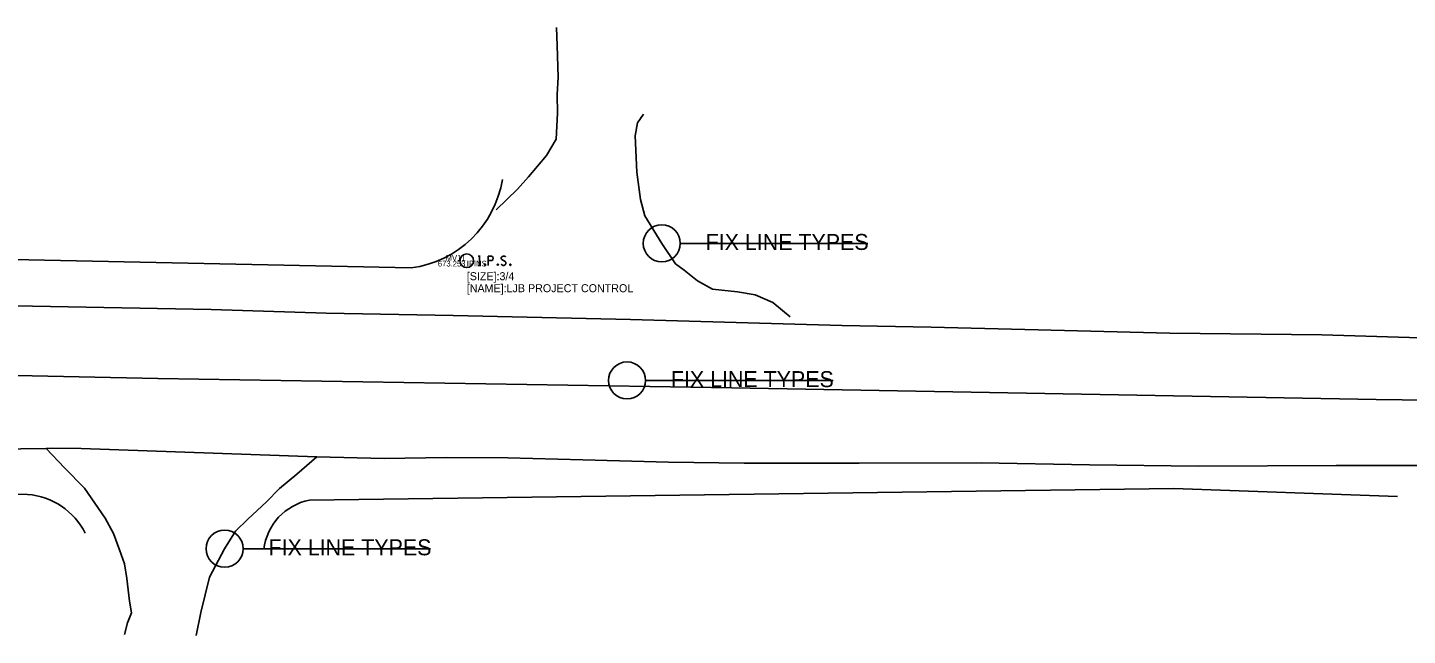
# Model space of a CAD drawing. Extents: x 1659932 to 1663108, y 619867 to 620611.
# Drawn here: x 1662378.6 to 1662620, y 620165.8 to 620272.2 of the extents above; entities that cross this region are included whole.
import ezdxf

# ---------------------------------------------------------------- set-up
doc = ezdxf.new("R2010")
doc.units = 0
for name, color, linetype in [('PM_X_CL_Dashed', 7, 'Continuous'), ('PV_X_Driveway', 7, 'Continuous'), ('PV_X_EOP', 7, 'Continuous'), ('RD_X_GR_Lt', 7, 'Continuous'), ('RD_X_GR_Rt', 7, 'Continuous'), ('RS_Raster1', 7, 'Continuous'), ('SC_Scratch6', 7, 'Continuous'), ('SV_P_Mon_Cells_Set_Text', 7, 'Continuous'), ('SV_X_Text_Comment', 7, 'Continuous'), ('SV_X_Text_Elevation', 7, 'Continuous'), ('SV_X_Text_Name', 7, 'Continuous')]:
    doc.layers.add(name, color=color, linetype=linetype)

msp = doc.modelspace()

# ---------------------------------------------------------------- linework, layer by layer
at = {"layer": 'PM_X_CL_Dashed'}
msp.add_lwpolyline([(1661548.68, 620227.77), (1661669.96, 620225.42), (1661783.14, 620222.83), (1661893.22, 620220.99), (1661995.64, 620218.69), (1662098.65, 620216.83), (1662208.49, 620214.49), (1662310.47, 620212.73), (1662401.36, 620210.77), (1662501.77, 620209.17), (1662614.52, 620207.13), (1662727.83, 620205.67), (1662841.02, 620204.32), (1662955.43, 620202.56), (1663049.21, 620201.36)], dxfattribs=at)
at = {"layer": 'PV_X_Driveway'}
for points in [[(1662460.54, 620240.32), (1662464.25, 620243.92), (1662466.2, 620246.07), (1662469.37, 620249.77), (1662471.06, 620252.67), (1662471.28, 620257.18), (1662471.19, 620260.47), (1662471.38, 620263.53), (1662471.2, 620269.05), (1662471.11, 620272.17)], [(1662511.97, 620221.55), (1662508.94, 620224.1), (1662505.83, 620225.43), (1662502.79, 620225.92), (1662498.37, 620226.39), (1662495.76, 620227.86), (1662493.42, 620229.75), (1662491.9, 620230.87), (1662489.52, 620234.43), (1662486.58, 620239.22), (1662485.8, 620242.11), (1662485.16, 620246.91), (1662484.89, 620253.23), (1662485.25, 620255.52), (1662486.3, 620257.05)], [(1662381.78, 620198.56), (1662385.01, 620195.16), (1662388.52, 620191.58), (1662392.1, 620186.32), (1662393.58, 620183.64), (1662394.66, 620180.8), (1662395.49, 620178.34), (1662395.91, 620175.79), (1662396.39, 620171.8), (1662396.76, 620169.81), (1662396.05, 620168.02), (1662395.49, 620166)], [(1662429.15, 620197.06), (1662425.64, 620194.03), (1662422.64, 620191.53), (1662420.35, 620189.19), (1662417.11, 620186.15), (1662414.93, 620184.09), (1662413.03, 620181.01), (1662411.42, 620178.02), (1662410.38, 620176.03), (1662408.87, 620169.82), (1662408.07, 620165.84)]]:
    msp.add_lwpolyline(points, dxfattribs=at)
at = {"layer": 'PV_X_EOP'}
for points in [[(1662356.1, 620223.94), (1662379.4, 620223.45), (1662410.67, 620222.83), (1662430.81, 620222.24), (1662453.03, 620221.83), (1662484.05, 620221.11), (1662521.05, 620220.08), (1662536.67, 620219.77), (1662553.06, 620219.35), (1662578.43, 620218.71), (1662605, 620218.4), (1662626.13, 620217.78), (1662672.55, 620217.65), (1662695.2, 620217.2), (1662709.6, 620217.07), (1662729.62, 620215.99), (1662750.02, 620215.7)], [(1662368.44, 620198.38), (1662381.78, 620198.56), (1662382.87, 620198.57), (1662387.9, 620198.53), (1662429.15, 620197.06), (1662440.92, 620196.76), (1662451.85, 620196.96), (1662462.59, 620196.88), (1662475.72, 620196.55), (1662490.67, 620196.16), (1662503.91, 620195.98), (1662524.07, 620195.98), (1662545.42, 620196), (1662564.38, 620195.66), (1662583.42, 620195.47), (1662607.51, 620195.55), (1662625.5, 620195.59), (1662642.9, 620195.66), (1662666.6, 620195.5), (1662681.6, 620195.32), (1662697.07, 620195.69), (1662737.7, 620195.47), (1662777.34, 620194.96)]]:
    msp.add_lwpolyline(points, dxfattribs=at)
at = {"layer": 'RD_X_GR_Lt'}
msp.add_line((1662112.15, 620237.06), (1662445.65, 620230.14), dxfattribs=at)
msp.add_arc((1662443.24, 620248.64), 18.66, 277.4288, 350.6729, dxfattribs=at)
at = {"layer": 'RD_X_GR_Rt'}
for p, q in [((1662114.92, 620196.42), (1662378.55, 620190.5)), ((1662427.87, 620189.49), (1662579.1, 620191.55)), ((1662579.1, 620191.55), (1662618.25, 620190.16))]:
    msp.add_line(p, q, dxfattribs=at)
for centre, radius, start, end in [((1662377.61, 620178.2), 12.33, 26.5223, 85.6298), ((1662429.75, 620179.74), 9.93, 100.9088, 173.3472)]:
    msp.add_arc(centre, radius, start, end, dxfattribs=at)
at = {"layer": 'RS_Raster1'}
for points in [[(1662457.42, 620232.18), (1662457.77, 620232.18)], [(1662457.6, 620230.58), (1662457.6, 620232.18)], [(1662459.16, 620230.58), (1662459.16, 620232.18), (1662459.69, 620232.18), (1662459.75, 620232.17), (1662459.82, 620232.15), (1662459.86, 620232.12), (1662459.89, 620232.1), (1662459.94, 620232.03), (1662459.97, 620231.97), (1662459.99, 620231.87), (1662459.99, 620231.72), (1662459.98, 620231.67), (1662459.96, 620231.59), (1662459.91, 620231.5), (1662459.87, 620231.47), (1662459.84, 620231.44), (1662459.78, 620231.42), (1662459.69, 620231.4), (1662459.16, 620231.4)], [(1662462.17, 620232.07), (1662462.15, 620232.1), (1662462.12, 620232.12), (1662462.02, 620232.16), (1662461.9, 620232.18), (1662461.81, 620232.18), (1662461.78, 620232.18), (1662461.63, 620232.15), (1662461.51, 620232.07), (1662461.43, 620231.97), (1662461.41, 620231.87), (1662461.41, 620231.79), (1662461.43, 620231.69), (1662461.52, 620231.61), (1662462.13, 620231.23), (1662462.18, 620231.18), (1662462.21, 620231.13), (1662462.23, 620231.05), (1662462.23, 620230.98), (1662462.22, 620230.9), (1662462.21, 620230.85), (1662462.18, 620230.79), (1662462.16, 620230.74), (1662462.14, 620230.7), (1662462.11, 620230.66), (1662462.07, 620230.64), (1662462.03, 620230.61), (1662462, 620230.6), (1662461.9, 620230.58), (1662461.74, 620230.58), (1662461.64, 620230.61), (1662461.5, 620230.7), (1662461.41, 620230.77)], [(1662457.42, 620230.58), (1662457.77, 620230.58)], [(1662458.56, 620230.8), (1662458.61, 620230.8), (1662458.65, 620230.77), (1662458.68, 620230.72), (1662458.68, 620230.66), (1662458.65, 620230.61), (1662458.61, 620230.58), (1662458.56, 620230.58), (1662458.52, 620230.61), (1662458.49, 620230.66), (1662458.49, 620230.72), (1662458.52, 620230.77), (1662458.56, 620230.8)], [(1662460.81, 620230.8), (1662460.86, 620230.8), (1662460.89, 620230.77), (1662460.93, 620230.72), (1662460.93, 620230.66), (1662460.89, 620230.61), (1662460.86, 620230.58), (1662460.81, 620230.58), (1662460.77, 620230.61), (1662460.74, 620230.66), (1662460.74, 620230.72), (1662460.77, 620230.77), (1662460.81, 620230.8)], [(1662462.99, 620230.8), (1662463.04, 620230.8), (1662463.08, 620230.77), (1662463.11, 620230.72), (1662463.11, 620230.66), (1662463.08, 620230.61), (1662463.04, 620230.58), (1662462.99, 620230.58), (1662462.96, 620230.61), (1662462.92, 620230.66), (1662462.92, 620230.72), (1662462.96, 620230.77), (1662462.99, 620230.8)]]:
    msp.add_lwpolyline(points, dxfattribs=at)
msp.add_circle((1662455.4, 620231.38), 1.2, dxfattribs=at)
at = {"layer": 'SC_Scratch6'}
for p, q in [((1662492.77, 620234.43), (1662525.57, 620234.43)), ((1662486.68, 620210.44), (1662519.49, 620210.44)), ((1662416.28, 620181.01), (1662449.08, 620181.01))]:
    msp.add_line(p, q, dxfattribs=at)
for centre in [(1662489.52, 620234.43), (1662483.44, 620210.44), (1662413.03, 620181.01)]:
    msp.add_circle(centre, 3.24, dxfattribs=at)

# ---------------------------------------------------------------- texts
for p in [(1662497.2, 620233.27), (1662491.11, 620209.27), (1662420.71, 620179.85)]:
    msp.add_text('FIX LINE TYPES', height=2.8, dxfattribs=at).set_placement(p)
at = {"layer": 'SV_P_Mon_Cells_Set_Text'}
for s, p in [('[SIZE]:3/4', (1662455.4, 620227.98)), ('[NAME]:LJB PROJECT CONTROL', (1662455.4, 620225.88))]:
    msp.add_text(s, height=1.4, dxfattribs=at).set_placement(p)
at = {"layer": 'SV_X_Text_Comment'}
msp.add_text('IPINS', height=1, dxfattribs=at).set_placement((1662455.4, 620230.38))
at = {"layer": 'SV_X_Text_Elevation'}
msp.add_text('673.253', height=1, dxfattribs=at).set_placement((1662450.34, 620230.38))
at = {"layer": 'SV_X_Text_Name'}
msp.add_text('MV11', height=1, dxfattribs=at).set_placement((1662451.7, 620231.38))

doc.saveas('drawing.dxf')
